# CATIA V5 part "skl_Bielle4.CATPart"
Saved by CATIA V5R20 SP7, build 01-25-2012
Part number: skl_Equerre7
Publications: "Axe_Equerre7Patin3", "Axe_Equerre7Socle", "Axe_Equerre7Bielle5", "Point.1", "Point.3", "Point.2", "Plan.1"
Bounding box of the stored display mesh (mm): x 0 to 20, y -47 to -10.033, z 111 to 134.34
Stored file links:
  J:\ACHTUNG2\skl_Bielle4.CATPart
  J:\cmilovidofIAO\skl_IAO.CATProduct
  J:\ACHTUNG2\skl_IAO2.CATProduct
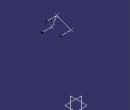
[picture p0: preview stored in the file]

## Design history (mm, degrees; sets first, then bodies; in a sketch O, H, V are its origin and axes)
Set1
  Point1 to Point3: linked copy from another document
  Plane1: linked copy from another document
Body1 (main body)
  Line1: type PtPt, FirstPoint Point1, SecondPoint Point2
  Line2: type PtPt, FirstPoint Point2, SecondPoint Point3
  Line3: type Normal, RefPoint Point2, RefSkin Plane1, Start 0, End 20
  Line4: type Normal, RefPoint Point1, RefSkin Plane1, Start 0, End 20
  Line5: type Normal, RefPoint Point3, RefSkin Plane1, Start 0, End 20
